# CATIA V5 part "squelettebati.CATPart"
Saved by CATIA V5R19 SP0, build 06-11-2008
Part number: squelette bati
Bounding box of the stored display mesh (mm): x 0 to 0, y 0 to 39, z -12 to 31
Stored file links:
  C:\Users\Gauthier\Documents\IFMA\IAO\TP2\squelettebati.CATPart
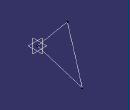
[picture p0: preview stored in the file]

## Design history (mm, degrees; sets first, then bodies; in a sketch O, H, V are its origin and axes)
Set1
  Line1: type PtPt, SecondPoint Point2, FirstPoint Point1
  Point1: stored without definition
  Point2: stored without definition
  Line2: type PtPt, SecondPoint Point4, FirstPoint Point3
  Point3: stored without definition
  Point4: stored without definition
  Line3: type PtPt, SecondPoint Point6, FirstPoint Point5
  Point5: stored without definition
  Point6: stored without definition
Body1 (main body)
